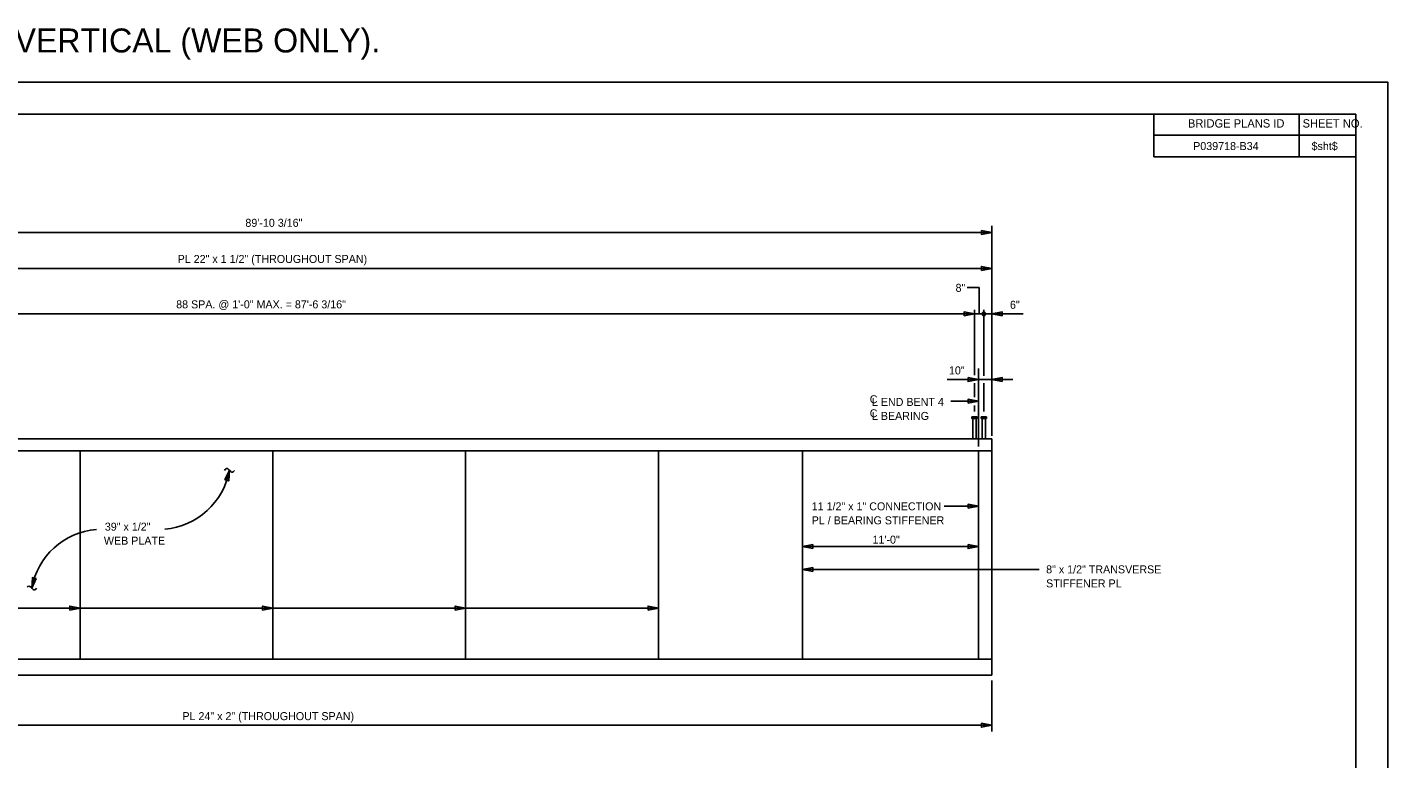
# Model space of a CAD drawing. Extents: x -383 to -161, y -356 to -94.
# Drawn here: x -246.2 to -161.2, y -141.8 to -96.1 of the extents above; entities that cross this region are included whole.
import ezdxf

# ---------------------------------------------------------------- set-up
doc = ezdxf.new("R2010")
doc.units = 0
for name, color, linetype in [('BR_AUTO DIMENSION', 7, 'Continuous'), ('BR_BORDER LINES', 7, 'Continuous'), ('BR_CENTER LINES', 7, 'Continuous'), ('BR_STRUCTURAL STEEL', 7, 'Continuous'), ('BR_TEXT', 7, 'Continuous'), ('Default', 7, 'Continuous'), ('Level 31', 7, 'Continuous')]:
    doc.layers.add(name, color=color, linetype=linetype)

msp = doc.modelspace()

# ---------------------------------------------------------------- linework, layer by layer
at = {"layer": 'BR_AUTO DIMENSION'}
for p, q in [((-185.922, -121.593), (-185.922, -108.463)), ((-275.77, -108.876), (-185.922, -108.876)), ((-275.77, -111.134), (-185.922, -111.134)), ((-187.006, -117.796), (-187.006, -113.71)), ((-186.422, -117.843), (-186.422, -113.71)), ((-187.006, -113.971), (-274.603, -113.971)), ((-183.969, -113.971), (-187.006, -113.971)), ((-188.702, -118.071), (-184.616, -118.071)), ((-187.006, -119.179), (-187.006, -118.298)), ((-186.422, -120.06), (-186.422, -118.298)), ((-186.756, -119.433), (-188.479, -119.433)), ((-187.006, -120.06), (-187.006, -119.697)), ((-186.756, -125.99), (-188.9, -125.99)), ((-197.756, -128.508), (-186.756, -128.508)), ((-197.756, -129.95), (-182.958, -129.95)), ((-206.756, -132.351), (-288.443, -132.351)), ((-185.922, -136.871), (-185.922, -140.076)), ((-275.77, -139.676), (-185.922, -139.676))]:
    msp.add_line(p, q, dxfattribs=at)
for points in [[(-186.572, -108.751), (-185.922, -108.876), (-186.572, -109.001)], [(-186.572, -111.259), (-185.922, -111.134), (-186.572, -111.009)], [(-187.656, -114.096), (-187.006, -113.971), (-187.656, -113.846)], [(-185.272, -114.096), (-185.922, -113.971), (-185.272, -113.846)], [(-187.406, -117.946), (-186.756, -118.071), (-187.406, -118.196)], [(-185.272, -118.196), (-185.922, -118.071), (-185.272, -117.946)], [(-187.406, -119.558), (-186.756, -119.433), (-187.406, -119.308)], [(-233.847, -124.344), (-233.564, -123.746), (-233.604, -124.406)], [(-187.406, -126.115), (-186.756, -125.99), (-187.406, -125.865)], [(-197.106, -128.633), (-197.756, -128.508), (-197.106, -128.383)], [(-187.406, -128.383), (-186.756, -128.508), (-187.406, -128.633)], [(-197.106, -130.075), (-197.756, -129.95), (-197.106, -129.825)], [(-245.633, -130.513), (-245.915, -131.111), (-245.875, -130.451)], [(-243.541, -132.476), (-242.891, -132.351), (-243.541, -132.226)], [(-231.496, -132.476), (-230.846, -132.351), (-231.496, -132.226)], [(-219.451, -132.476), (-218.801, -132.351), (-219.451, -132.226)], [(-207.406, -132.476), (-206.756, -132.351), (-207.406, -132.226)], [(-186.572, -139.551), (-185.922, -139.676), (-186.572, -139.801)]]:
    msp.add_lwpolyline(points, close=True, dxfattribs=at)
msp.add_lwpolyline([(-186.714, -113.971), (-186.714, -112.325), (-187.454, -112.325)], dxfattribs=at)
msp.add_circle((-186.422, -113.971), 0.111, dxfattribs=at)
for centre, start, end in [((-237.988, -122.942), 274.96239, 349.7037), ((-241.491, -131.915), 94.96239, 169.7037)]:
    msp.add_arc(centre, 4.497, start, end, dxfattribs=at)
at = {"layer": 'BR_BORDER LINES'}
for p, q in [((-163.178, -101.489), (-297.843, -101.489)), ((-175.788, -104.156), (-175.788, -101.489)), ((-166.722, -104.156), (-166.722, -101.489)), ((-163.178, -185.489), (-163.178, -101.489)), ((-175.788, -102.808), (-163.178, -102.808)), ((-166.722, -102.808), (-163.178, -102.808)), ((-163.178, -104.156), (-175.788, -104.156))]:
    msp.add_line(p, q, dxfattribs=at)
at = {"layer": 'BR_CENTER LINES'}
msp.add_line((-186.756, -117.387), (-186.756, -122.256), dxfattribs=at)
at = {"layer": 'BR_STRUCTURAL STEEL'}
for p, q in [((-275.77, -121.787), (-185.922, -121.787)), ((-185.922, -121.787), (-185.922, -122.537)), ((-275.77, -122.537), (-185.922, -122.537)), ((-242.891, -122.537), (-242.891, -135.537)), ((-230.846, -122.537), (-230.846, -135.537)), ((-218.801, -122.537), (-218.801, -135.537)), ((-206.756, -122.537), (-206.756, -135.537)), ((-197.756, -122.537), (-197.756, -135.537)), ((-186.756, -122.537), (-186.756, -135.537)), ((-185.922, -122.537), (-185.922, -135.537)), ((-275.77, -135.537), (-185.922, -135.537)), ((-185.922, -136.537), (-185.922, -135.537)), ((-275.77, -136.537), (-185.922, -136.537))]:
    msp.add_line(p, q, dxfattribs=at)
at = {"layer": 'BR_TEXT'}
for p, q in [((-233.824, -123.693), (-233.866, -123.754)), ((-233.482, -123.82), (-233.645, -123.671)), ((-233.249, -123.754), (-233.279, -123.8)), ((-245.997, -131.037), (-245.834, -131.186)), ((-245.655, -131.164), (-245.613, -131.103))]:
    msp.add_line(p, q, dxfattribs=at)
for centre, radius, start, end in [((-233.726, -123.746), 0.111, 43.45189, 151.73747), ((-233.389, -123.739), 0.125, 221.00704, 330.80591), ((-246.091, -131.118), 0.125, 41.00704, 150.80591), ((-245.753, -131.111), 0.111, 223.45189, 331.73747)]:
    msp.add_arc(centre, radius, start, end, dxfattribs=at)
at = {"layer": 'Default'}
for p, q in [((-187.178, -120.412), (-187.178, -120.506)), ((-187.178, -120.412), (-186.834, -120.412)), ((-187.178, -120.506), (-186.834, -120.506)), ((-187.115, -120.506), (-187.115, -121.787)), ((-186.896, -120.506), (-186.896, -121.787)), ((-186.834, -120.412), (-186.834, -120.506)), ((-186.594, -120.412), (-186.594, -120.506)), ((-186.594, -120.412), (-186.25, -120.412)), ((-186.594, -120.506), (-186.25, -120.506)), ((-186.532, -120.506), (-186.532, -121.787)), ((-186.313, -120.506), (-186.313, -121.787)), ((-186.25, -120.412), (-186.25, -120.506))]:
    msp.add_line(p, q, dxfattribs=at)
at = {"layer": 'Level 31'}
msp.add_lwpolyline([(-305.176, -187.489), (-161.176, -187.489), (-161.176, -99.489), (-305.176, -99.489)], close=True, dxfattribs=at)

# ---------------------------------------------------------------- texts
at = {"layer": 'BR_AUTO DIMENSION'}
for s, p in [('89\'-10 3/16"', (-232.566, -108.53)), ('PL 22" x 1 1/2" (THROUGHOUT SPAN)', (-236.8, -110.788)), ('8"', (-188.186, -112.593)), ('88 SPA. @ 1\'-0" MAX. = 87\'-6 3/16"', (-236.89, -113.625)), ('6"', (-184.787, -113.652)), ('10"', (-188.6, -117.752)), ('39" x 1/2" ', (-241.35, -127.518)), ('WEB PLATE', (-241.408, -128.393)), ('11\'-0"', (-193.377, -128.329)), ('PL 24" x 2" (THROUGHOUT SPAN)', (-236.501, -139.357))]:
    msp.add_text(s, height=0.5, rotation=360, dxfattribs=at).set_placement(p)
at = {"layer": 'BR_TEXT'}
for s, height, p in [('EXAGGERATED BY 6 VERTICAL (FLANGES ONLY) AND BY 4 VERTICAL (WEB ONLY).', 1.5, (-305.065, -97.636)), ('BRIDGE PLANS ID', 0.52, (-173.663, -102.327)), ('SHEET NO.', 0.52, (-166.499, -102.327)), ('P039718-B34', 0.5, (-173.338, -103.732)), ('$sht$', 0.5, (-165.939, -103.732))]:
    msp.add_text(s, height=height, dxfattribs=at).set_placement(p)
for s, p in [('C', (-193.549, -119.556)), ('L END BENT 4', (-193.414, -119.723)), ('C', (-193.549, -120.431)), ('L BEARING', (-193.414, -120.598)), ('11 1/2" x 1" CONNECTION ', (-197.177, -126.247)), ('PL / BEARING STIFFENER', (-197.177, -127.122)), ('8" x 1/2" TRANSVERSE ', (-182.526, -130.187)), ('STIFFENER PL', (-182.526, -131.062))]:
    msp.add_text(s, height=0.5, rotation=360, dxfattribs=at).set_placement(p)

doc.saveas('drawing.dxf')
